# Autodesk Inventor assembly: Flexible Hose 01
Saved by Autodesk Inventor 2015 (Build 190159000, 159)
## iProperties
Created: 2013-02
Part Number: Flexible Hose 01
Document SubType Name: Assembly
Designer: Marci
Name: Hydraulic Hose - No Fittings
ActiveState: True
PipeType: Flexible Hose
Material: UnInitValue
Standard: UnInitValue
FittingMaterial: UnInitValue
FittingStandard: UnInitValue
RouteDirection90: UnInitValue
RouteDirection45: UnInitValue
IsFlanged: UnInitValue
IsButtWelded: UnInitValue
DiameterType: Nominal
Diameter: 1/4
Schedule: ID=0.25
OD: 1,4986
ID: 0,635
Ending: UnInitValue
IntermediateSegmentsMin: UnInitValue
IntermediateSegmentsMax: UnInitValue
IntermediateSegmentsInc: UnInitValue
TerminationSegmentsMin: UnInitValue
TerminationSegmentsMax: UnInitValue
TerminationSegmentsInc: UnInitValue
RoundUpValue: 0.125 in
DefaultBendRadius: UnInitValue
BendRadius: 0.500 in
PipingComponentColor: Blue (Flat)
PipeKey: v3#d489867e-ac9b-47ea-b952-0a1b885f66be#1
CouplingKey: UnInitValue
Elbow90Key: UnInitValue
Elbow45Key: UnInitValue
SuppressStartFitting: True
SuppressEndFitting: True
FlangeKey: UnInitValue
GasketKey: UnInitValue
Gap: UnInitValue
UseSubASM: True
_ComponentInfo: <CS><C N="Pipe" R="0,749300" OR="0,749300" IR="0,317500" PL="PL" PartType="pipe" SymKey="" PN="Parker hidraulikatömlő - No Skive 1/4"><CO N="1"><FE V="0"/><FD V
ShowGap: UnInitValue
MixedUnits: UnInitValue
UseFlangsForCouplings: UnInitValue
IsSelfDraining: UnInitValue
ElbowCustomKey: UnInitValue
Angle: UnInitValue
Author: Marci
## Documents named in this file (3)
- C:\Users\Andrew Almeida\Documents\Projeto WS2015\WS2015 CAD Data ANLAS\01\Pneumatic System\Engine\Pneumatikus hajtás\Teljes hajtás\AIP\Tube and Pipe\Run06\Teljes hajtás.Hose01.iam
- C:\Users\Andrew Almeida\Documents\Projeto WS2015\WS2015 CAD Data ANLAS\01\Pneumatic System\Engine\Pneumatikus hajtás\Teljes hajtás\AIP\Tube and Pipe\Run06\Teljes hajtás.Hose01.ipt
- C:\Users\Andrew Almeida\Documents\Projeto WS2015\WS2015 CAD Data ANLAS\01\Pneumatic System\Engine\Pneumatikus hajtás\Teljes hajtás\AIP\Tube and Pipe\Run06\pifhose.1360342447854.ipt
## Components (2 placed, 2 different names)
1. Hose01
2. Flexible Hose:1
